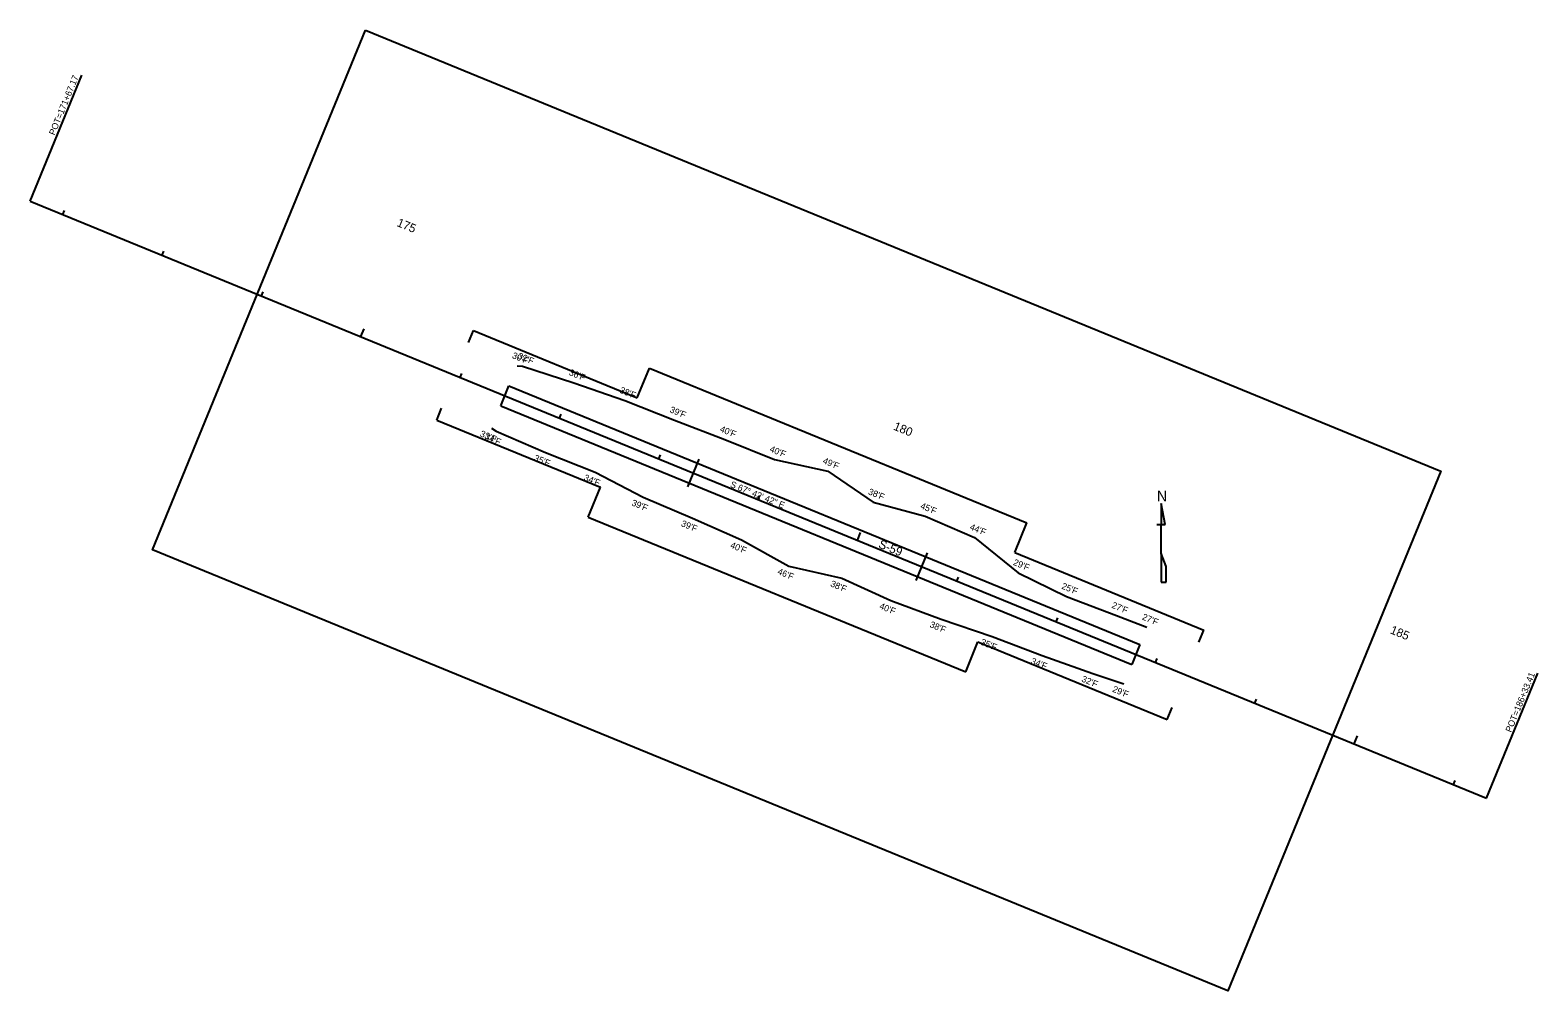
# Model space of a CAD drawing. Extents: x 1904865 to 1906752, y 1106408 to 1110518.
# Drawn here: x 1904865 to 1906270, y 1109624 to 1110518 of the extents above; entities that cross this region are included whole.
import ezdxf

# ---------------------------------------------------------------- set-up
doc = ezdxf.new("R2010")
doc.units = 0
for name, color, linetype in [('GN_Clip', 7, 'Continuous'), ('RD_EX_Misc', 7, 'Continuous'), ('RD_HC_Cl', 7, 'Continuous'), ('RD_HC_Data', 7, 'Continuous'), ('RD_HC_Data_Tic', 7, 'Continuous'), ('RD_HC_TX_Sta50', 7, 'Continuous'), ('RD_PD_Bridge', 7, 'Continuous'), ('RD_PD_CstnLmt', 7, 'Continuous'), ('RD_PD_CstnLmt_TX', 7, 'Continuous'), ('RD_PD_Final_TrvlWay', 7, 'Continuous'), ('RD_PD_RW', 7, 'Continuous'), ('RD_SHT_TX', 7, 'Continuous')]:
    doc.layers.add(name, color=color, linetype=linetype)

msp = doc.modelspace()

# ---------------------------------------------------------------- linework, layer by layer
at = {"layer": 'GN_Clip'}
msp.add_lwpolyline([(1905177.5, 1110518.4), (1906179.3, 1110107.7), (1905980.9, 1109623.6), (1904979.1, 1110034.3)], close=True, dxfattribs=at)
at = {"layer": 'RD_EX_Misc'}
for p, q in [((1905922.5, 1110058), (1905918.6, 1110077.6)), ((1905918.6, 1110077.6), (1905918.6, 1110077.6)), ((1905918.6, 1110077.6), (1905918.6, 1110058)), ((1905914.7, 1110058), (1905918.6, 1110058)), ((1905918.6, 1110030.8), (1905918.6, 1110058)), ((1905918.6, 1110058), (1905922.5, 1110058)), ((1905922.5, 1110058), (1905922.5, 1110058.3)), ((1905923.5, 1110018.8), (1905918.6, 1110030.8)), ((1905918.6, 1110030.8), (1905918.6, 1110004.1)), ((1905923.5, 1110004.1), (1905923.5, 1110019)), ((1905923.5, 1110019), (1905923.5, 1110018.8)), ((1905918.6, 1110004.1), (1905923.5, 1110004.1))]:
    msp.add_line(p, q, dxfattribs=at)
at = {"layer": 'RD_HC_Cl'}
msp.add_line((1904865.2, 1110359.1), (1906221.9, 1109803), dxfattribs=at)
at = {"layer": 'RD_HC_Data'}
for p, q in [((1904865.2, 1110359.1), (1904913.3, 1110476.4)), ((1906221.9, 1109803), (1906269.6, 1109919.5))]:
    msp.add_line(p, q, dxfattribs=at)
at = {"layer": 'RD_HC_Data_Tic'}
for p, q in [((1904895.6, 1110346.7), (1904897.1, 1110350.4)), ((1904988.1, 1110308.7), (1904989.6, 1110312.4)), ((1905080.6, 1110270.8), (1905082.1, 1110274.5)), ((1905173.2, 1110232.9), (1905176.2, 1110240.3)), ((1905265.7, 1110194.9), (1905267.2, 1110198.6)), ((1905358.2, 1110157), (1905359.7, 1110160.7)), ((1905450.7, 1110119.1), (1905452.3, 1110122.8)), ((1905543.3, 1110081.2), (1905544.8, 1110084.9)), ((1905635.8, 1110043.2), (1905638.8, 1110050.6)), ((1905728.3, 1110005.3), (1905729.8, 1110009)), ((1905820.9, 1109967.4), (1905822.4, 1109971.1)), ((1905913.4, 1109929.5), (1905914.9, 1109933.2)), ((1906005.9, 1109891.5), (1906007.4, 1109895.2)), ((1906098.4, 1109853.6), (1906101.5, 1109861)), ((1906191, 1109815.7), (1906192.5, 1109819.4))]:
    msp.add_line(p, q, dxfattribs=at)
at = {"layer": 'RD_PD_Bridge'}
for p, q in [((1905477.7, 1110092.9), (1905488.3, 1110118.8)), ((1905690.5, 1110005.7), (1905701.1, 1110031.6))]:
    msp.add_line(p, q, dxfattribs=at)
at = {"layer": 'RD_PD_CstnLmt'}
for p, q in [((1905318.7, 1110205.7), (1905323.9, 1110205.3)), ((1905323.9, 1110205.3), (1905371.7, 1110189.9)), ((1905371.7, 1110189.9), (1905419, 1110173.4)), ((1905419, 1110173.4), (1905465.5, 1110155.2)), ((1905465.5, 1110155.2), (1905512.2, 1110137.2)), ((1905294.9, 1110147.6), (1905299.2, 1110144.8)), ((1905299.2, 1110144.8), (1905345.1, 1110125)), ((1905512.2, 1110137.2), (1905558.6, 1110118.6)), ((1905345.1, 1110125), (1905391.6, 1110106.7)), ((1905558.6, 1110118.6), (1905608.1, 1110107.6)), ((1905391.6, 1110106.7), (1905436.1, 1110083.4)), ((1905608.1, 1110107.6), (1905650.4, 1110078.8)), ((1905436.1, 1110083.4), (1905482.2, 1110064)), ((1905650.4, 1110078.8), (1905699, 1110065.6)), ((1905482.2, 1110064), (1905527.9, 1110043.8)), ((1905699, 1110065.6), (1905745, 1110046)), ((1905527.9, 1110043.8), (1905571.9, 1110019.3)), ((1905745, 1110046), (1905785.5, 1110013)), ((1905571.9, 1110019.3), (1905621.3, 1110007.9)), ((1905621.3, 1110007.9), (1905666.8, 1109987.1)), ((1905785.5, 1110013), (1905830.5, 1109990.9)), ((1905666.8, 1109987.1), (1905713.8, 1109969.9)), ((1905830.5, 1109990.9), (1905877.2, 1109973.1)), ((1905877.2, 1109973.1), (1905905.5, 1109962.2)), ((1905713.8, 1109969.9), (1905761.2, 1109953.6)), ((1905761.2, 1109953.6), (1905808, 1109935.9)), ((1905808, 1109935.9), (1905855.1, 1109919.2)), ((1905855.1, 1109919.2), (1905884, 1109909.7))]:
    msp.add_line(p, q, dxfattribs=at)
at = {"layer": 'RD_PD_Final_TrvlWay'}
for p, q in [((1905303.5, 1110168.6), (1905311.1, 1110187.1)), ((1905311.1, 1110187.1), (1905898.9, 1109946.2)), ((1905303.5, 1110168.6), (1905891.3, 1109927.7)), ((1905898.9, 1109946.2), (1905891.3, 1109927.7))]:
    msp.add_line(p, q, dxfattribs=at)
at = {"layer": 'RD_PD_RW'}
for p, q in [((1905273.6, 1110227.4), (1905278.1, 1110238.5)), ((1905278.1, 1110238.5), (1905430.7, 1110176)), ((1905430.7, 1110176), (1905442, 1110203.7)), ((1905442, 1110203.7), (1905793.6, 1110059.6)), ((1905244, 1110155.2), (1905248.5, 1110166.3)), ((1905244, 1110155.2), (1905396.5, 1110092.7)), ((1905385.1, 1110064.9), (1905396.5, 1110092.7)), ((1905385.1, 1110064.9), (1905736.7, 1109920.8)), ((1905782.3, 1110031.8), (1905793.6, 1110059.6)), ((1905782.3, 1110031.8), (1905958.5, 1109959.6)), ((1905953.9, 1109948.5), (1905958.5, 1109959.6)), ((1905736.7, 1109920.8), (1905748.1, 1109948.6)), ((1905748.1, 1109948.6), (1905924.3, 1109876.3)), ((1905924.3, 1109876.3), (1905928.9, 1109887.4))]:
    msp.add_line(p, q, dxfattribs=at)

# ---------------------------------------------------------------- texts
at = {"layer": 'RD_EX_Misc'}
msp.add_text('N', height=10, dxfattribs=at).set_placement((1905914.7, 1110079.5))
at = {"layer": 'RD_HC_Data'}
for s, rotation, p in [('POT=171+67.17', 67.7118, (1904888, 1110420)), ('S 67%%d 42\' 42" E', 337.7118, (1905516.7, 1110093.1)), ('POT=186+33.41', 67.7118, (1906244.7, 1109863.9))]:
    msp.add_text(s, height=6, rotation=rotation, dxfattribs=at).set_placement(p)
at = {"layer": 'RD_HC_TX_Sta50'}
for s, p in [('175', (1905206.1, 1110336.1)), ('180', (1905668.7, 1110146.5)), ('185', (1906131.4, 1109956.8))]:
    msp.add_text(s, height=8, rotation=337.7118, dxfattribs=at).set_placement(p)
at = {"layer": 'RD_PD_CstnLmt_TX'}
for s, p in [("30'F", (1905313.6, 1110213.2)), ("32'F", (1905318.8, 1110212.8)), ("36'F", (1905366.6, 1110197.4)), ("38'F", (1905413.8, 1110180.9)), ("39'F", (1905460.4, 1110162.7)), ("33'F", (1905283.7, 1110140.3)), ("34'F", (1905288, 1110137.5)), ("40'F", (1905507.1, 1110144.7)), ("40'F", (1905553.5, 1110126.1)), ("35'F", (1905333.9, 1110117.7)), ("49'F", (1905603, 1110115.1)), ("34'F", (1905380.4, 1110099.4)), ("38'F", (1905645.3, 1110086.3)), ("39'F", (1905424.9, 1110076)), ("45'F", (1905693.9, 1110073.1)), ("39'F", (1905471, 1110056.7)), ("44'F", (1905739.9, 1110053.5)), ("40'F", (1905516.8, 1110036.5)), ("46'F", (1905560.8, 1110012)), ("29'F", (1905780.4, 1110020.5)), ("38'F", (1905610.1, 1110000.6)), ("25'F", (1905825.4, 1109998.4)), ("27'F", (1905872.1, 1109980.6)), ("40'F", (1905655.7, 1109979.8)), ("27'F", (1905900.4, 1109969.7)), ("38'F", (1905702.6, 1109962.6)), ("35'F", (1905750, 1109946.3)), ("34'F", (1905796.8, 1109928.6)), ("32'F", (1905844, 1109911.9)), ("29'F", (1905872.8, 1109902.4))]:
    msp.add_text(s, height=6, rotation=337.7118, dxfattribs=at).set_placement(p)
at = {"layer": 'RD_SHT_TX'}
msp.add_text('S-59', height=8, rotation=337.7118, dxfattribs=at).set_placement((1905654.8, 1110036.7))

doc.saveas('drawing.dxf')
